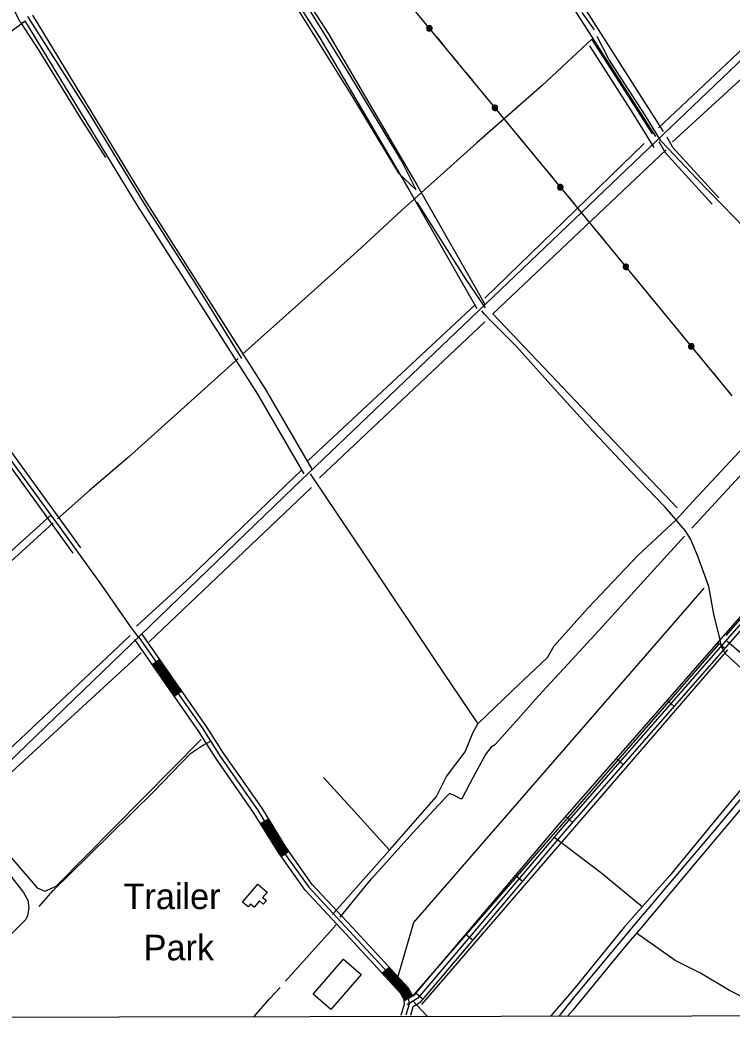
# Model space of a CAD drawing. Extents: x 3324125 to 3362000, y 600753 to 626151.
# Drawn here: x 3330393 to 3332702, y 606134 to 609371 of the extents above; entities that cross this region are included whole.
import ezdxf

# ---------------------------------------------------------------- set-up
doc = ezdxf.new("R2010")
doc.units = 0
for name, color, linetype in [('V-BLDG-IDEN', 7, 'Continuous'), ('V-BLDG-OTLN', 7, 'Continuous'), ('V-DTCH-CNTR', 7, 'Continuous'), ('V-GRID-FRAM', 7, 'Continuous'), ('V-ROAD-CNTR', 7, 'Continuous'), ('V-TOPO-SHOR', 7, 'Continuous'), ('V-UTIL-LINE', 7, 'Continuous')]:
    doc.layers.add(name, color=color, linetype=linetype)

msp = doc.modelspace()

# ---------------------------------------------------------------- linework, layer by layer
at = {"layer": 'V-BLDG-OTLN'}
for points in [[(3331115.1, 606510.6), (3331164.5, 606569), (3331194.9, 606543.2), (3331180.2, 606525.8), (3331192.3, 606515.6), (3331182.4, 606504), (3331169.7, 606514.8), (3331152.2, 606494.3), (3331140.6, 606504.1), (3331133.2, 606495.3)], [(3331344.1, 606211.5), (3331442, 606325.3), (3331499.5, 606275.9), (3331401.6, 606162.1)]]:
    msp.add_lwpolyline(points, close=True, dxfattribs=at)
at = {"layer": 'V-DTCH-CNTR'}
msp.add_line((3332215.3, 609395.2), (3332255.1, 609338.7), dxfattribs=at)
for points in [[(3330394.4, 609365.1), (3330359.3, 609431.6), (3330272.7, 609579.3), (3330184.1, 609725.7), (3330093.1, 609880.9)], [(3331267.8, 609449), (3331472.5, 609119.4), (3331621.1, 608874.1), (3331678.4, 608820), (3331631.5, 608913.5), (3331463.2, 609193.3), (3331297.5, 609461.2)], [(3330394.4, 609365.1), (3330454.7, 609271.6), (3330593.2, 609046.8), (3330670.2, 608925)], [(3330417.8, 609382.4), (3330612.7, 609076.2), (3330796.5, 608774.8), (3330961.7, 608516.3), (3331111.2, 608272.8)], [(3332471.8, 608978.7), (3332420.6, 609062), (3332302.5, 609244.3), (3332264.6, 609316.9)], [(3332240.4, 609287.4), (3332380.4, 609067.9), (3332449.3, 608957.2)], [(3333315.1, 608074.9), (3333298.7, 608095.5), (3333195.8, 608203.1), (3333107.2, 608296.5), (3333066.5, 608344.1), (3333060.6, 608350.9), (3333045.3, 608368.8), (3332953.5, 608469.6), (3332849.7, 608585.5), (3332708, 608732.9), (3332588.2, 608855.4), (3332495.4, 608954.5), (3332471.8, 608978.7)], [(3329717.4, 608863.9), (3329815.7, 608725.9), (3329976.9, 608496.8), (3330158.2, 608234.9), (3330341.9, 607972.7), (3330493, 607765.2), (3330520.6, 607728.6), (3330657.8, 607538.6), (3330750.3, 607404.3), (3330777.1, 607368.3)], [(3331679.8, 608780.6), (3331839.2, 608529.7), (3331901.3, 608437.6)], [(3332669.6, 607336.3), (3332662.4, 607364.7), (3332643.5, 607443.9), (3332627.4, 607534.1), (3332592.6, 607629.4), (3332567.5, 607688.6), (3332549.9, 607715.7), (3332530.4, 607739.5), (3332521.6, 607749.5), (3332484.3, 607792), (3332375.7, 607906), (3332253.5, 608035.8), (3332123.5, 608177.8), (3332003.8, 608312), (3331922.3, 608393.3), (3331899.8, 608417.4), (3331890.5, 608427.4)], [(3332521.6, 607749.5), (3332574.9, 607809.3), (3332726.4, 607971.2), (3332858.1, 608112.8), (3332885.1, 608162.2), (3333023.5, 608299), (3333066.5, 608344.1)], [(3331334.6, 607898.9), (3331513.7, 607632.4), (3331761.5, 607261.9), (3331878.1, 607088.4)], [(3330493, 607765.2), (3330365.4, 607650), (3330206.2, 607502.7), (3329988.6, 607315.3), (3329894.4, 607231.5), (3329874.6, 607214), (3329775.7, 607112.6), (3329599.2, 606970.2), (3329471.7, 606851.9), (3329328.5, 606720.7), (3329304.7, 606699.5), (3329211.7, 606616.5), (3329050.9, 606474.8), (3328876, 606321.6), (3328739, 606175), (3328695, 606135.3)], [(3331878.1, 607088.4), (3331989.1, 607195.7), (3332104.5, 607303.8), (3332125.9, 607341.6), (3332235.7, 607464.5), (3332397.2, 607633.9), (3332521.6, 607749.5)], [(3332669.6, 607336.3), (3332680.1, 607316.6), (3332916.4, 607098.7), (3332809.8, 606969.7), (3332670, 606803.6), (3332500.4, 606597), (3332411.3, 606495.6), (3332352.9, 606429.1), (3332189.2, 606228), (3332114.3, 606141.3)], [(3332800.4, 607258.8), (3332686.2, 607355.6)], [(3331406.5, 606470), (3331592, 606678.6), (3331593, 606679.8), (3331743.9, 606852.9), (3331776.1, 606917.5), (3331836.7, 606997.9), (3331862.4, 607061), (3331878.1, 607088.4)], [(3330455.9, 606496.7), (3330501.1, 606548.2), (3330615.4, 606660), (3330826.2, 606867.9), (3330946.7, 606992.4), (3330987.9, 607020.1), (3331009.6, 607030.7)], [(3331592, 606678.6), (3331478.7, 606803.5), (3331377.4, 606914.5)], [(3332779.5, 606870.7), (3332589.3, 606644.7), (3332406.8, 606426), (3332392.9, 606409.9), (3332358.9, 606370.5), (3332185.6, 606160.5), (3332169.7, 606141.4)], [(3332411.3, 606495.6), (3332279.8, 606602.8), (3332124.5, 606721.3)], [(3332855.9, 606142.6), (3332694.3, 606224.3), (3332599.8, 606279.9), (3332517.6, 606321.3), (3332392.9, 606409.9)], [(3331714, 606140.6), (3331666.2, 606190.9)]]:
    msp.add_lwpolyline(points, dxfattribs=at)
at = {"layer": 'V-GRID-FRAM'}
msp.add_lwpolyline([(3328210, 624318.2), (3328233.8, 606134.5), (3359834, 606189.7), (3359794.3, 624373.3), (3328210, 624318.2)], dxfattribs=at)
at = {"layer": 'V-ROAD-CNTR'}
for p, q in [((3332657.2, 607352.2), (3332679.7, 607332.4)), ((3330821.8, 607280.9), (3330846.4, 607298)), ((3330893.3, 607178.3), (3330917.9, 607195.5)), ((3332492.6, 607164), (3332515.1, 607144.3)), ((3332328, 606975.9), (3332350.5, 606956.1)), ((3331173.3, 606765.2), (3331198.8, 606781)), ((3332163.4, 606787.7), (3332185.9, 606767.9)), ((3331240.2, 606658.5), (3331264.7, 606675.9)), ((3332001.2, 606597.1), (3332024.1, 606577.7)), ((3331839.6, 606406.3), (3331862.5, 606387)), ((3331568, 606279.5), (3331590, 606299.9)), ((3331638.8, 606190), (3331667.3, 606206.4)), ((3331678, 606215.6), (3331700.9, 606196.2))]:
    msp.add_line(p, q, dxfattribs=at)
for points in [[(3333821.8, 610283.1), (3331280.8, 607855.1)], [(3332454.9, 608993.5), (3332213.3, 609371.4), (3331825.1, 609973.4), (3331637.3, 610276.9)], [(3332480.1, 609009.7), (3332238.6, 609387.6), (3331850.5, 609989.4), (3331661.5, 610294.8)], [(3331032.5, 609829.8), (3331365.5, 609313.3), (3331654.2, 608821.1), (3331875, 608434.9)], [(3331056.7, 609847.7), (3331391.1, 609329), (3331680.2, 608836.1), (3331901, 608449.7)], [(3329736.5, 608868.5), (3329934.5, 609014.4), (3330410.3, 609368.1)], [(3331315, 607899.6), (3331164.5, 608157.1), (3330772.5, 608772.7), (3330410.3, 609368.1)], [(3331340.9, 607914.7), (3331190.1, 608172.8), (3330797.9, 608788.6), (3330434.5, 609386)], [(3331667.2, 606206.4), (3331673.7, 606210.5), (3332139.1, 606759.9), (3333317.1, 608106.6), (3334159.6, 609074.5)], [(3334170.9, 609064.6), (3333328.4, 608096.7), (3332150.5, 606750.2), (3331683.7, 606199), (3331649, 606177.1)], [(3331668.7, 606171.8), (3331693.6, 606187.5), (3332161.8, 606740.4), (3333339.7, 608086.9), (3334182.2, 609054.8)], [(3332464.7, 608976.7), (3332485.2, 608940.9), (3332637.8, 608773.9)], [(3332490.7, 608991.6), (3332509.6, 608958.7), (3332659.9, 608794.1)], [(3329712.3, 608850.7), (3329882.8, 608611.5), (3330092.7, 608294.2), (3330565.1, 607641.7)], [(3329736.5, 608868.5), (3329907.6, 608628.5), (3330117.4, 608311.2), (3330589.4, 607659.3)], [(3331280.8, 607855.1), (3330257.2, 606869.4), (3330242.7, 606853.2), (3330234.5, 606839.2), (3330230.6, 606824.6), (3330227.4, 606804.9), (3330235, 606784), (3330243.7, 606755.5), (3330261.4, 606724.8), (3330404.3, 606541.9), (3330419, 606516.5), (3330422.2, 606491.6), (3330418.1, 606466.5), (3330411.9, 606454), (3330094.9, 606140.8)], [(3331629.5, 606143.6), (3331640.1, 606180.8), (3331637.8, 606197.6), (3331628.5, 606214.1), (3331463.5, 606392.3), (3331318, 606549.1), (3331231.4, 606670.9), (3331153.1, 606798.1), (3331028.7, 606976.7), (3330973.3, 607063.5), (3330765.3, 607361.9)], [(3330777.6, 607370.5), (3330985.8, 607071.8), (3331041.2, 606985), (3331165.6, 606806.3), (3331243.9, 606679.2), (3331329.6, 606558.5), (3331474.5, 606402.5), (3331640.8, 606223), (3331652.2, 606202.4), (3331655.4, 606179.7), (3331645, 606143.5)], [(3331666.9, 606206.1), (3331666.7, 606207.3), (3331653, 606231.9), (3331485.5, 606412.7), (3331341.3, 606568), (3331256.4, 606687.5), (3331178.2, 606814.6), (3331053.7, 606993.3), (3330998.3, 607080.1), (3330789.9, 607379.1)], [(3330910.5, 607190.3), (3330839, 607292.9)], [(3330913, 607192), (3330841.5, 607294.6)], [(3330915.4, 607193.8), (3330843.9, 607296.3)], [(3330895.7, 607180), (3330824.2, 607282.6)], [(3330898.2, 607181.7), (3330826.7, 607284.3)], [(3330900.7, 607183.5), (3330829.2, 607286)], [(3330903.1, 607185.2), (3330831.6, 607287.7)], [(3330905.6, 607186.9), (3330834.1, 607289.4)], [(3330908, 607188.6), (3330836.6, 607291.2)], [(3331254.9, 606668.9), (3331246.4, 606680.8), (3331188.6, 606774.7)], [(3331257.3, 606670.7), (3331248.9, 606682.5), (3331191.2, 606776.3)], [(3331259.8, 606672.4), (3331251.4, 606684.2), (3331193.7, 606777.8)], [(3331262.2, 606674.2), (3331253.9, 606685.8), (3331196.3, 606779.4)], [(3331242.6, 606660.3), (3331233.9, 606672.6), (3331175.9, 606766.8)], [(3331245.1, 606662), (3331236.4, 606674.2), (3331178.4, 606768.4)], [(3331247.5, 606663.7), (3331238.9, 606675.9), (3331181, 606770)], [(3331250, 606665.5), (3331241.4, 606677.5), (3331183.5, 606771.5)], [(3331252.4, 606667.2), (3331243.9, 606679.2), (3331186.1, 606773.1)], [(3331652.8, 606198), (3331652.2, 606202.4), (3331640.8, 606223), (3331579, 606289.7)], [(3331655.7, 606199.5), (3331655.1, 606203.4), (3331643.2, 606224.8), (3331581.2, 606291.7)], [(3331658.5, 606201.2), (3331658, 606204.4), (3331645.6, 606226.5), (3331583.4, 606293.8)], [(3331661.3, 606202.8), (3331660.9, 606205.4), (3331648.1, 606228.3), (3331585.6, 606295.8)], [(3331664.1, 606204.4), (3331663.8, 606206.3), (3331650.5, 606230.1), (3331587.8, 606297.8)], [(3331641.6, 606191.6), (3331640.7, 606198.6), (3331631, 606215.9), (3331570.2, 606281.5)], [(3331644.4, 606193.2), (3331643.6, 606199.5), (3331633.4, 606217.7), (3331572.4, 606283.6)], [(3331647.2, 606194.8), (3331646.5, 606200.5), (3331635.9, 606219.4), (3331574.6, 606285.6)], [(3331650, 606196.5), (3331649.3, 606201.5), (3331638.3, 606221.2), (3331576.8, 606287.6)], [(3331660.7, 606143.7), (3331668.7, 606171.8)]]:
    msp.add_lwpolyline(points, dxfattribs=at)
at = {"layer": 'V-TOPO-SHOR'}
for p, q in [((3332985.1, 609512.2), (3332463.5, 609021.3)), ((3333026, 609450.9), (3332509.5, 608975.3)), ((3331901, 608469.1), (3332417.5, 608970.2)), ((3331870.3, 608448.6), (3331328.3, 607942.4)), ((3331901, 608392.4), (3331364.1, 607886.1)), ((3332683.4, 607374.8), (3333291.9, 608075.3)), ((3330811.8, 607354.3), (3331338.5, 607855.4)), ((3330750.5, 607374.8), (3330239.1, 606894.1)), ((3331696.5, 606178.2), (3332688.5, 607328.8)), ((3331254.2, 606253.6), (3331418.3, 606436.7))]:
    msp.add_line(p, q, dxfattribs=at)
for points in [[(3332142.5, 606141.3), (3332189.7, 606199.9), (3332388.8, 606439.1), (3332647.1, 606743.3), (3332885.3, 607030.3), (3332964.9, 607127.7), (3333082.9, 607271.9), (3333155.8, 607364.5), (3333227.2, 607447), (3333303.6, 607548.5), (3333478.5, 607758.5), (3333603.3, 607906), (3333755.9, 608096.6), (3333910.1, 608281.4), (3334012.5, 608409.1), (3334171, 608598.6), (3334328, 608789.7), (3334494.4, 608986.2), (3334638.5, 609160.8), (3334721.2, 609259.3), (3334803.3, 609355.5)], [(3332444.5, 609001.2), (3332374, 609112.4), (3332289, 609244.9), (3332247.5, 609308.6), (3332086.2, 609158.7), (3331875.3, 608972.9), (3331631, 608753.4), (3331486.6, 608619.8), (3331306, 608458.5), (3331114.8, 608286.7)], [(3332489, 608949.7), (3331926.6, 608417.9), (3332524.8, 607789)], [(3331101, 608272.8), (3330947.2, 608135.3), (3330743.8, 607952.4), (3330618.9, 607845.4), (3330515.2, 607753)], [(3332572.3, 607723.5), (3332674.8, 607834.7), (3332790, 607959.7), (3332905.6, 608087.6), (3332964.4, 608156), (3333052.1, 608243.9), (3333095.6, 608291.5)], [(3331307.8, 607911.7), (3330944.8, 607564), (3330770.9, 607405.5)], [(3330500.6, 607740.5), (3330387.5, 607636), (3330199, 607467.3), (3330052.2, 607337.4), (3329924, 607222.1), (3329796.9, 607108.2), (3329671.1, 606994.6), (3329572.3, 606900.5), (3329536.3, 606870.8), (3329504.8, 606846.6), (3329443.5, 606783.6), (3329390.8, 606740.2), (3329317.2, 606677.5), (3329261.7, 606623.3), (3329176.1, 606548.1), (3329079.2, 606458.5), (3328957.6, 606352.7), (3328840.5, 606248.5), (3328743.2, 606155.9), (3328721.3, 606135.3)], [(3331431.9, 606461.9), (3331533.2, 606586.1), (3331667.7, 606735.3), (3331777, 606854.3), (3331786.2, 606862.6), (3331799.4, 606857.9), (3331821.3, 606846.6), (3331827.2, 606845.9), (3331864.3, 606916.3), (3331903.2, 606987.7), (3331924.2, 607015.8), (3331935.2, 607022.4), (3332009.7, 607105.8), (3332074.6, 607179.1), (3332182.8, 607296.5), (3332280.8, 607403), (3332416.4, 607552.2), (3332548.8, 607697.3)], [(3331619.8, 606270.3), (3331670.9, 606444.1), (3332550.4, 607456.6), (3332611.8, 607528.2)], [(3331665.8, 606203.8), (3332657.8, 607344.1), (3332657.8, 607354.3)], [(3330786.3, 607318.5), (3330285.1, 606858.3), (3330264.7, 606822.5), (3330269.8, 606786.7), (3330290.3, 606740.7), (3330448.8, 606556.6), (3330474.3, 606546.4), (3330510.1, 606561.7), (3330980.6, 607037.3)], [(3331153.1, 606139.6), (3331203.7, 606197.8), (3331236.6, 606233.8)]]:
    msp.add_lwpolyline(points, dxfattribs=at)
at = {"layer": 'V-UTIL-LINE'}
for points in [[(3328236.3, 613587.3), (3328405.4, 613379.6), (3328937.8, 612727.6), (3329480.1, 612077.2), (3330016.7, 611428.3), (3330555.9, 610771.6), (3331085.8, 610130.8), (3331625.2, 609459.8), (3332162.6, 608808.1), (3332702, 608152.5)], [(3331720.9, 609343.8), (3331721.7, 609346.5), (3331719.5, 609345.8), (3331718.8, 609343.1), (3331720.9, 609341.1), (3331723.6, 609343.1), (3331724.2, 609347.8), (3331720.3, 609349.6), (3331715.9, 609347.6), (3331715.2, 609343.1), (3331717.3, 609339.1), (3331722, 609338.2), (3331726.4, 609341.5), (3331727.8, 609349.5), (3331725.1, 609351.7), (3331721.7, 609352.7), (3331718.3, 609352.4), (3331715.2, 609350.7), (3331712.9, 609348), (3331711.9, 609344.6), (3331712.3, 609341.1), (3331713.9, 609338), (3331716.7, 609335.8), (3331720, 609334.8), (3331723.5, 609335.2), (3331726.6, 609336.8), (3331728.8, 609339.5), (3331729.8, 609342.9), (3331729.5, 609346.4), (3331727.8, 609349.5)], [(3331745.7, 609313.7), (3331767.3, 609287.5)], [(3331792.8, 609256.6), (3331814.4, 609230.4)], [(3331839.9, 609199.5), (3331861.5, 609173.3)], [(3331886.9, 609142.4), (3331908.6, 609116.2)], [(3331933.4, 609086.1), (3331934.2, 609088.9), (3331932, 609088.1), (3331931.3, 609085.4), (3331933.4, 609083.4), (3331936.1, 609085.4), (3331936.7, 609090.1), (3331932.8, 609091.9), (3331928.4, 609090), (3331927.7, 609085.4), (3331929.8, 609081.4), (3331934.5, 609080.5), (3331938.9, 609083.8), (3331940.3, 609091.8), (3331937.6, 609094), (3331934.2, 609095.1), (3331930.8, 609094.7), (3331927.7, 609093), (3331925.4, 609090.3), (3331924.4, 609087), (3331924.8, 609083.5), (3331926.4, 609080.4), (3331929.2, 609078.1), (3331932.5, 609077.1), (3331936, 609077.5), (3331939.1, 609079.1), (3331941.3, 609081.9), (3331942.3, 609085.2), (3331942, 609088.7), (3331940.3, 609091.8)], [(3331958.2, 609056), (3331979.8, 609029.8)], [(3332005.3, 608998.9), (3332026.9, 608972.7)], [(3332052.4, 608941.8), (3332074, 608915.6)], [(3332099.4, 608884.7), (3332121.1, 608858.5)], [(3332145.9, 608828.4), (3332146.7, 608831.2), (3332144.5, 608830.4), (3332143.8, 608827.8), (3332145.9, 608825.7), (3332148.6, 608827.8), (3332149.2, 608832.4), (3332145.3, 608834.3), (3332140.9, 608832.3), (3332140.2, 608827.8), (3332142.3, 608823.8), (3332147, 608822.9), (3332151.4, 608826.1), (3332152.8, 608834.1), (3332150.1, 608836.4), (3332146.8, 608837.4), (3332143.3, 608837), (3332140.2, 608835.4), (3332137.9, 608832.6), (3332136.9, 608829.3), (3332137.3, 608825.8), (3332138.9, 608822.7), (3332141.7, 608820.5), (3332145, 608819.5), (3332148.5, 608819.8), (3332151.6, 608821.5), (3332153.8, 608824.2), (3332154.9, 608827.6), (3332154.5, 608831), (3332152.8, 608834.1)], [(3332170.7, 608798.3), (3332192.3, 608772.1)], [(3332217.7, 608741.2), (3332239.3, 608714.9)], [(3332264.7, 608684), (3332286.3, 608657.8)], [(3332311.7, 608626.9), (3332333.3, 608600.6)], [(3332358.1, 608570.5), (3332358.9, 608573.3), (3332356.7, 608572.5), (3332356, 608569.9), (3332358.1, 608567.8), (3332360.8, 608569.8), (3332361.4, 608574.5), (3332357.6, 608576.4), (3332353.1, 608574.4), (3332352.5, 608569.9), (3332354.5, 608565.9), (3332359.2, 608564.9), (3332363.7, 608568.2), (3332365.1, 608576.2), (3332362.3, 608578.4), (3332359, 608579.5), (3332355.5, 608579.1), (3332352.4, 608577.5), (3332350.2, 608574.7), (3332349.2, 608571.4), (3332349.5, 608567.9), (3332351.2, 608564.8), (3332353.9, 608562.6), (3332357.2, 608561.5), (3332360.7, 608561.9), (3332363.8, 608563.6), (3332366.1, 608566.3), (3332367.1, 608569.6), (3332366.7, 608573.1), (3332365.1, 608576.2)], [(3332382.9, 608540.4), (3332404.5, 608514.1)], [(3332429.9, 608483.2), (3332451.5, 608457)], [(3332476.9, 608426.1), (3332498.5, 608399.8)], [(3332523.9, 608369), (3332545.5, 608342.7)], [(3332570.3, 608312.6), (3332571.1, 608315.3), (3332568.9, 608314.6), (3332568.2, 608311.9), (3332570.3, 608309.9), (3332573, 608311.9), (3332573.6, 608316.6), (3332569.8, 608318.4), (3332565.3, 608316.5), (3332564.7, 608311.9), (3332566.7, 608307.9), (3332571.4, 608307), (3332575.9, 608310.3), (3332577.3, 608318.3), (3332574.5, 608320.5), (3332571.2, 608321.5), (3332567.7, 608321.2), (3332564.6, 608319.5), (3332562.4, 608316.8), (3332561.4, 608313.5), (3332561.7, 608310), (3332563.4, 608306.9), (3332566.1, 608304.6), (3332569.4, 608303.6), (3332572.9, 608304), (3332576, 608305.6), (3332578.3, 608308.3), (3332579.3, 608311.7), (3332578.9, 608315.2), (3332577.3, 608318.3)], [(3332595.1, 608282.5), (3332616.7, 608256.2)], [(3332642.1, 608225.3), (3332663.7, 608199.1)], [(3332689.1, 608168.2), (3332702, 608152.5)]]:
    msp.add_lwpolyline(points, dxfattribs=at)

# ---------------------------------------------------------------- texts
at = {"layer": 'V-BLDG-IDEN'}
for s, p in [('Trailer', (3330729.1, 606487.7)), ('Park', (3330794.3, 606321.7))]:
    msp.add_text(s, height=83, dxfattribs=at).set_placement(p)

doc.saveas('drawing.dxf')
